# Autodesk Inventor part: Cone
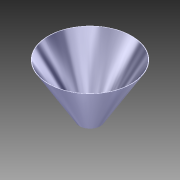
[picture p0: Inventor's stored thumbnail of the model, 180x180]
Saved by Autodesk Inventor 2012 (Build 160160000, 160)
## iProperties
Created: 2012-03
Part Number: Cone
Material: Stainless Steel
Document SubType Name: Modeling
Designer: Jonathan
Density: 8.08 g/cm^3
Mass: 4946.73 g
Surface Area: 4858.33 cm^2
Volume: 612.22 cm^3
Author: Jonathan
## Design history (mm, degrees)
sketch "Sketch3"
  geometry: L1 (0, 0)-(0, 254); L2 (0, 254)-(203.2, 254); L3 (203.2, 254)-(50.8, 0); L4 (50.8, 0)-(0, 0); L5 (0, -50.8)-(0, 304.8) reference
  constraints: 8 end point, 1 parallel, 1 perpendicular, 1 vertical
  dimensions: "d1" = 50.8 distance of L3.end L1.start; "d2" = 254 distance of L1.start L1.end; "d3" = 203.2 distance of L1.end L2.end
revolve "Revolution1" sketch "Sketch3" stored, may be unused: angle "d4" = 90 deg
shell "Shell2" dims "d6" = 2.54
body "Solid1"
